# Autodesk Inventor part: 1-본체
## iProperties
Created: 2015-01
Part Number: 1-본체
Document SubType Name: Modeling
Designer: Administrator
Density: 2.71 g/cm^3
Material: 알루미늄-6061
Mass: 1021.24 g
Surface Area: 1059.8 cm^2
Volume: 376.841 cm^3
Author: Administrator
